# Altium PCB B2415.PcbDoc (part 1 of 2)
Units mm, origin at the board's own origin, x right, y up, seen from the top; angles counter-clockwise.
Board outline 20.32 x 48.65 mm, 4 copper layers (Top Layer, Internal 1, Internal 2, Bottom Layer), stack 0.62 mm thick; 96 components, 71 nets, 432 pads, 386 vias.
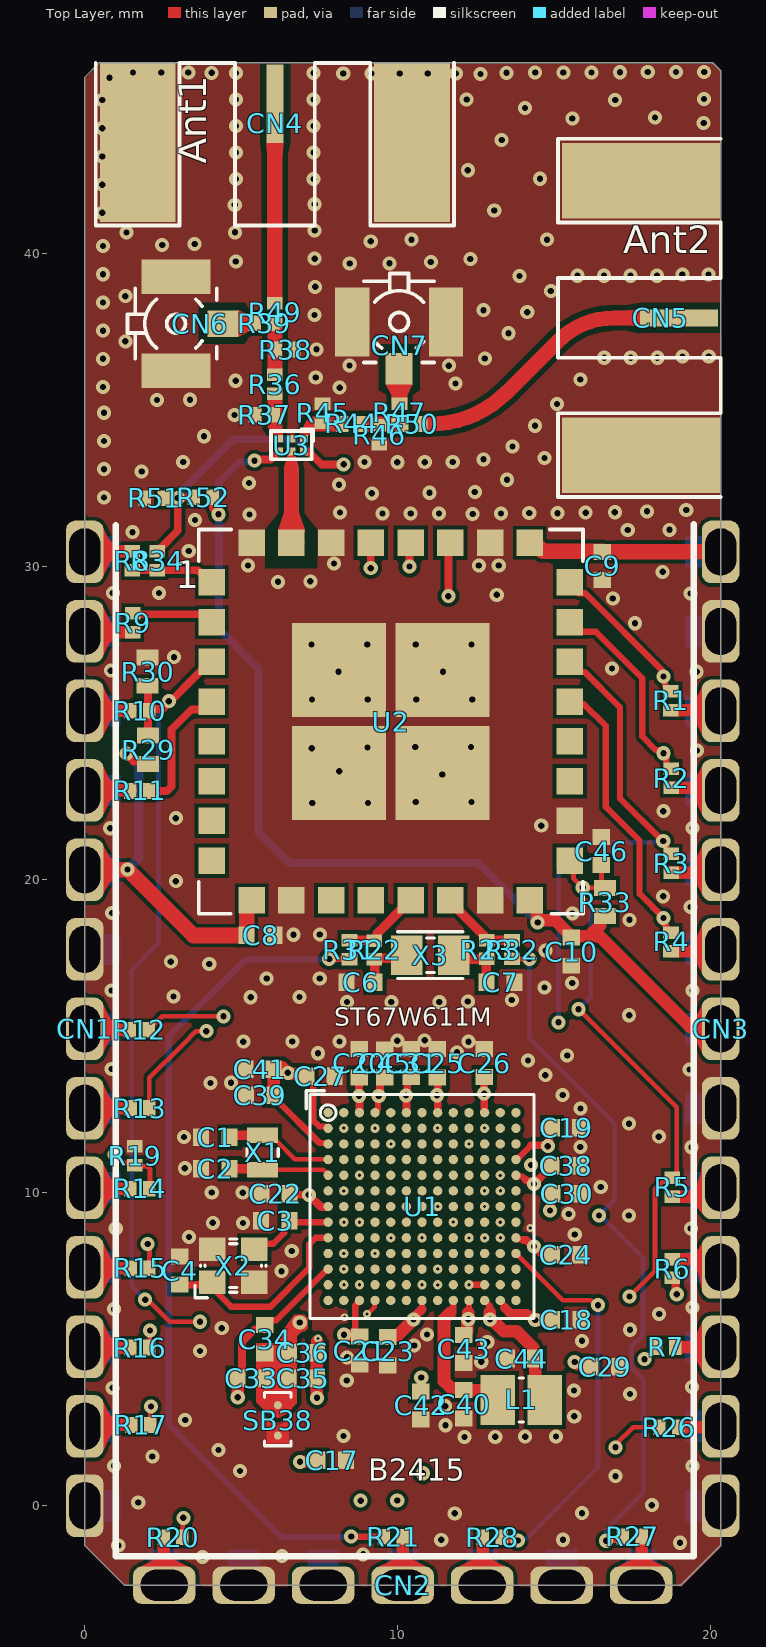
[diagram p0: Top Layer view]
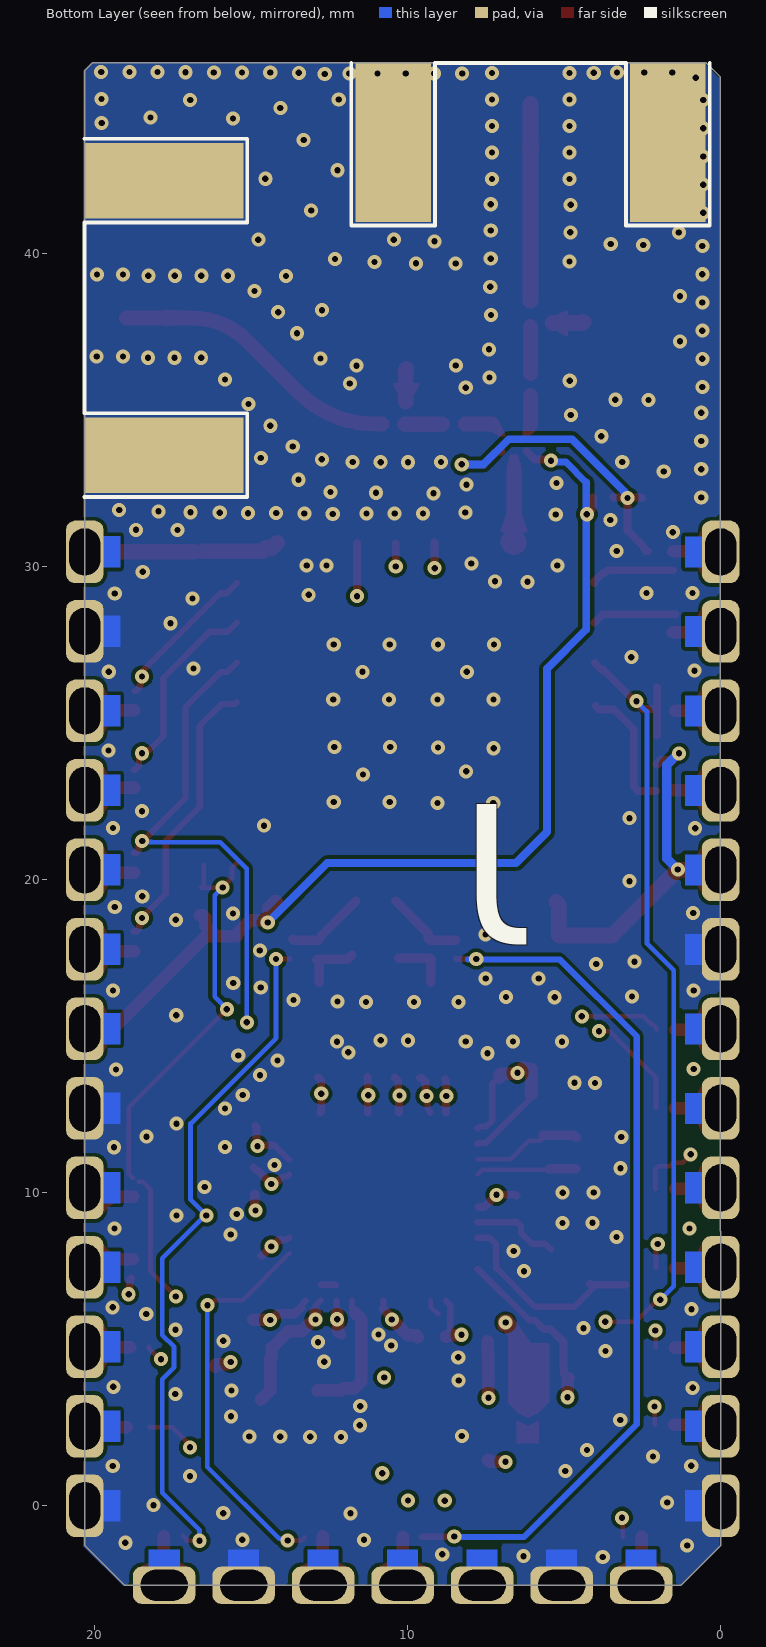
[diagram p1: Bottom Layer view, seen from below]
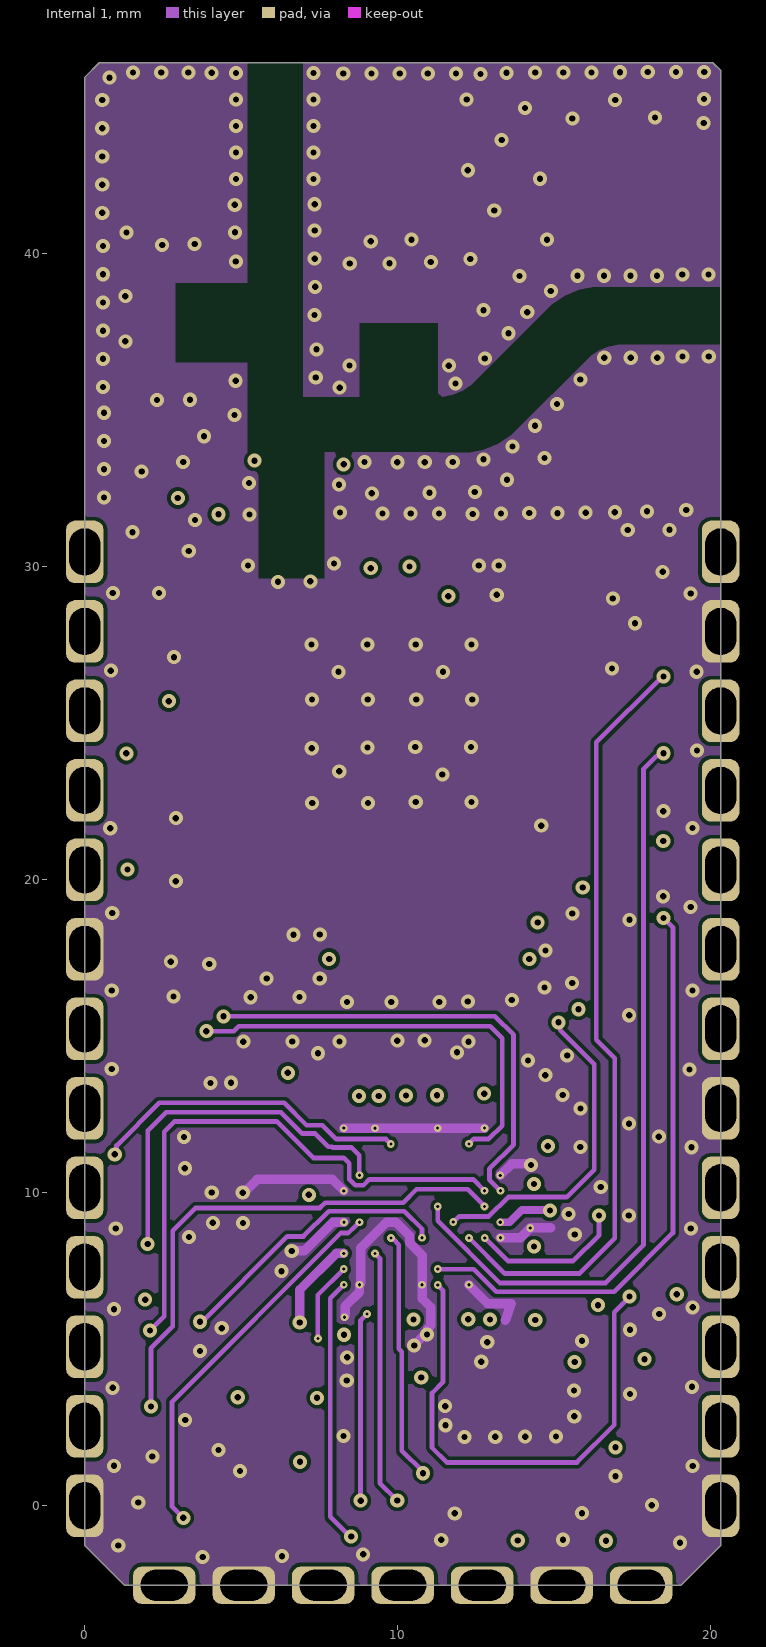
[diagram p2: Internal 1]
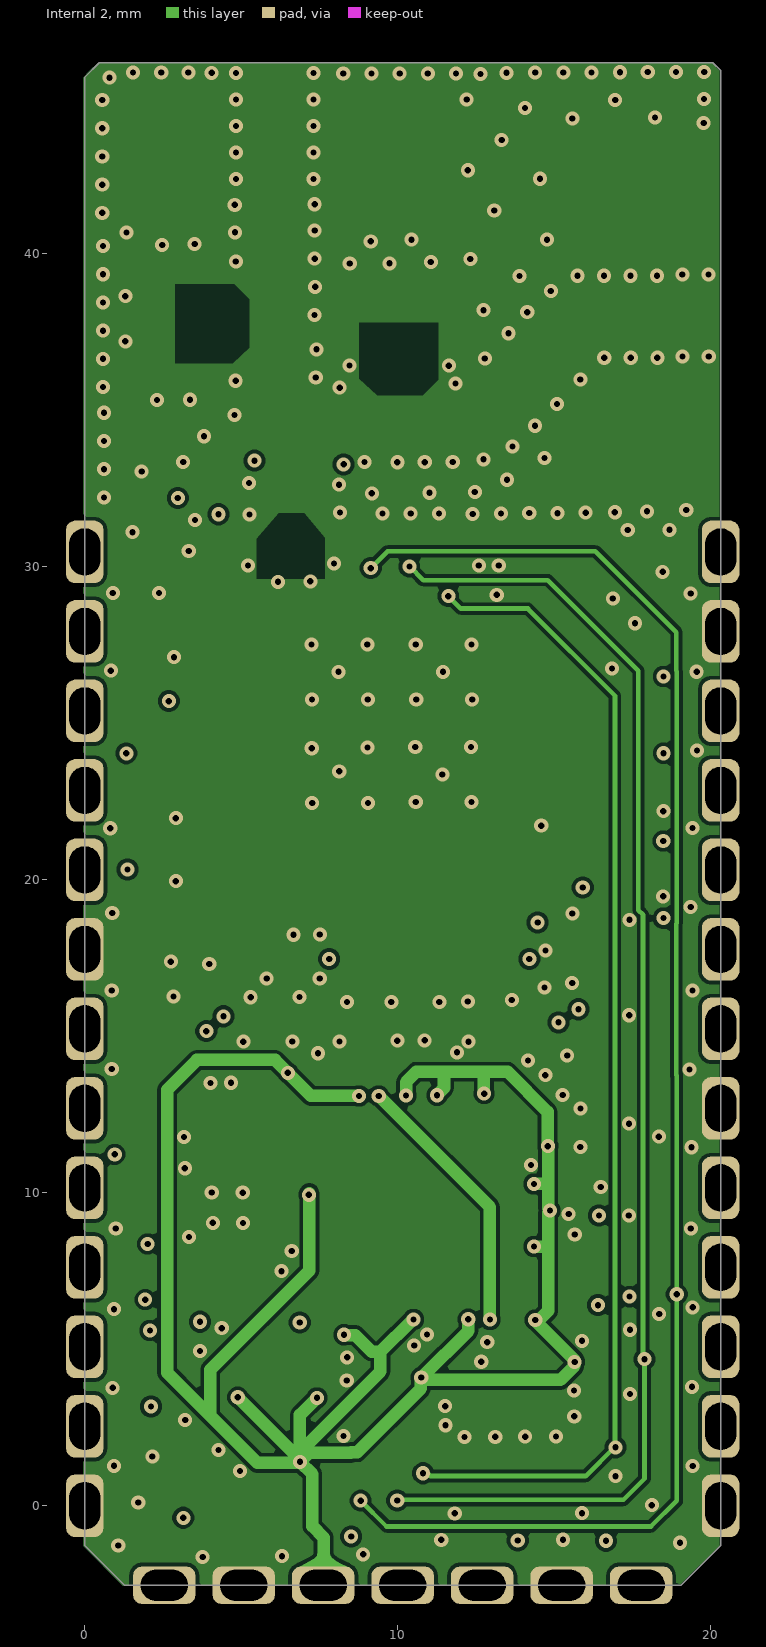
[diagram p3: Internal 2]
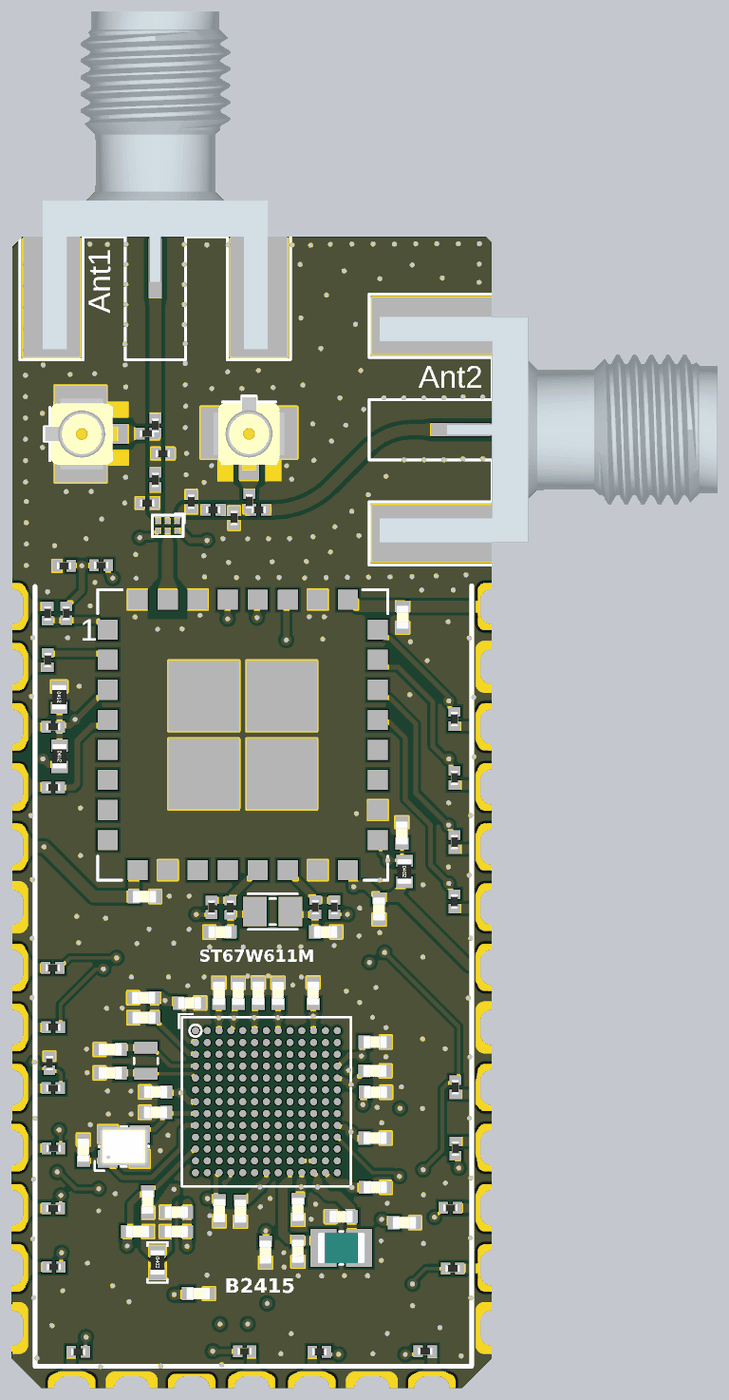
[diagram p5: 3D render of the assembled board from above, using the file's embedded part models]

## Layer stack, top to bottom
Top Solder: solder mask 0.0178, Solder Resist, Dk 3.2
Top Layer: signal copper 0.035
Dielectric 1: core 0.075, FR-4, Dk 4.5
Internal 1: signal copper 0.035
Dielectric 3: prepreg 0.335, Dk 4.5
Internal 2: signal copper 0.035
Dielectric 2: core 0.075, Dk 4.5
Bottom Layer: signal copper 0.03
Bottom Solder: solder mask 0.0178, Solder Resist, Dk 4.2

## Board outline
0,-1.27 0,8.758 0.008,8.767 0.008,45.651 0.467,46.11 20.07,46.11 20.32,45.86 20.32,-1.27 19.05,-2.54 1.27,-2.54

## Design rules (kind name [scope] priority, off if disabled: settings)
Clearance Clearance_SW [WithinRoom('STM32WW6_U575')] p1: gap=0.12 ignorepadtopadclearanceinfootprint=FALSE
Clearance "Schematic Clearance Constraint_4" [InNet('RF2')] p2: gap=0.17 ignorepadtopadclearanceinfootprint=FALSE
Clearance "Schematic Clearance Constraint_3" [InNet('RF1')] p3: gap=0.17 ignorepadtopadclearanceinfootprint=FALSE
Clearance "Schematic Clearance Constraint_20" [InNet('RF_Pin')] p4: gap=0.17 ignorepadtopadclearanceinfootprint=FALSE
Clearance "Schematic Clearance Constraint_19" [InNet('NetCN5_1')] p5: gap=0.17 ignorepadtopadclearanceinfootprint=FALSE
Clearance "Schematic Clearance Constraint_16" [InNet('RF1b')] p6: gap=0.17 ignorepadtopadclearanceinfootprint=FALSE
Clearance "Schematic Clearance Constraint_14" [InNet('RF2b')] p7: gap=0.17 ignorepadtopadclearanceinfootprint=FALSE
Clearance "Schematic Clearance Constraint_13" [InNet('NetCN7_1')] p8: gap=0.17 ignorepadtopadclearanceinfootprint=FALSE
Clearance "Schematic Clearance Constraint_8" [InNet('NetCN4_1')] p9: gap=0.17 ignorepadtopadclearanceinfootprint=FALSE
Clearance "Schematic Clearance Constraint_2" [InNet('NetCN6_1')] p10: gap=0.17 ignorepadtopadclearanceinfootprint=FALSE
Clearance [All] p11: gap=0.12 ignorepadtopadclearanceinfootprint=FALSE
ComponentClearance [All] p1 off: gap=0.2 collisioncheckmode=3 verticalgap=0.2 showdistances=FALSE
Height [All] p1 off: minheight=0 maxheight=25.4 prefheight=12.7
HoleSize [All] p1: absolutevalues=TRUE maxlimit=10 minlimit=0.025 maxpercent=80.000 minpercent=20.000
HoleToHoleClearance [All] p1: gap=0.127 allowstackedmicrovias=TRUE
MinimumSolderMaskSliver [All] p1: minsoldermaskwidth=0.1
PlaneConnect [All] p1: planeconnectstyle=Relief reliefexpansion=0.508 reliefentries=4 reliefconductorwidth=0.21 reliefairgap=0.21
PolygonConnect Path_RF [InNet('NetC12_2')] p1: connectstyle=Direct reliefconductorwidth=0.254 reliefentries=4 polygonreliefangle="90 Angle" airgapwidth=0.254
PolygonConnect PolygonConnect_via [IsVia] p2: connectstyle=Direct reliefconductorwidth=0.254 reliefentries=4 polygonreliefangle="90 Angle" airgapwidth=0.254
PolygonConnect General [All] p3: connectstyle=Direct reliefconductorwidth=0.2 reliefentries=4 polygonreliefangle="90 Angle" airgapwidth=0.2
RoutingVias [All] p1: holewidth=0.3 width=0.8 viastyle="Through Hole" minholewidth=0.1 minwidth=0.25 maxholewidth=3.5 maxwidth=6.5
SilkToSilkClearance [All] p1 off: silktosilkclearance=0.2
SilkToSolderMaskClearance [IsPad] p1 off: minsilkscreentomaskgap=0.2 clearancetoexposedcopper=TRUE
SolderMaskExpansion [All] p1: expansion=0.102 istentingtop=FALSE
Width [All] p1: maxlimit=6 minlimit=0.1 preferedwidth=0.3 minimp=50.000000 maximp=50.000000 favimp=50.000000
22 further rules are at their usual default settings.

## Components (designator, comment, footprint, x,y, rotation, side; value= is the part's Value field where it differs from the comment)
C1 "Capacitor" C0402 4.17,11.769 r0 top value=1.8pF
C2 "Capacitor" C0402 4.172,10.774 r0 top value=1.8pF
C3 "Capacitor" C0402 6.086,9.11 r0 top value=6.8pF
C4 "Capacitor" C0402 3.036,7.514 r270 top value=6.8pF
C6 "Capacitor" C0402 8.817,16.729 r180 top value=5.1pF
C7 "Capacitor" C0402 13.282,16.734 r180 top value=5.1pF
C8 "Capacitor" C0402 5.621,18.227 r0 top value=10uF
C9 "Capacitor" C0402 16.542,30.033 r270 top value=10uF
C10 "Capacitor" C0402 15.548,17.705 r90 top value=10uF
C17 "Capacitor" C0402 7.894,1.455 r180 top value=10uF
C18 "Capacitor" C0402 15.388,5.943 r180 top value=100nF
C19 "Capacitor" C0402 15.381,12.079 r180 top value=100nF
C20 "Capacitor" C0402 8.769,14.142 r270 top value=100nF
C21 "Capacitor" C0402 8.786,4.956 r90 top value=100nF
C22 "Capacitor" C0402 6.093,9.971 r0 top value=100nF
C23 "Capacitor" C0402 9.679,4.936 r90 top value=100nF
C24 "Capacitor" C0402 15.376,8.026 r180 top value=100nF
C25 "Capacitor" C0402 11.27,14.138 r270 top value=100nF
C26 "Capacitor" C0402 12.759,14.145 r270 top value=100nF
C27 "Capacitor" C0402 7.53,13.732 r180 top value=100nF
C29 "Capacitor" C0402 16.618,4.449 r180 top value=4.7uF
C30 "Capacitor" C0402 15.395,9.963 r180 top value=100nF
C31 "Capacitor" C0402 10.435,14.145 r270 top value=100nF
C33 "Capacitor" C0402 5.328,4.073 r180 top value=1uF
C34 "Capacitor" C0402 5.755,5.322 r90 top value=100nF
C35 "Capacitor" C0402 6.968,4.071 r0 top value=1uF
C36 "Capacitor" C0402 6.972,4.891 r0 top value=100nF
C38 "Capacitor" C0402 15.369,10.863 r180 top value=100nF
C39 "Capacitor" C0402 5.6,13.116 r0 top value=100nF
C40 "Capacitor" C0402 12.115,3.245 r90 top value=100pF
C41 "Capacitor" C0402 5.588,13.953 r0 top value=10uF
C42 "Capacitor" C0402 10.743,3.208 r90 top value=10uF
C43 "Capacitor" C0402 12.113,5.011 r90 top value=100nF
C44 "Capacitor" C0402 13.944,4.706 r0 top value=2.2uF
C45 "Capacitor" C0402 9.588,14.137 r270 top value=2.2uF
C46 "Capacitor" C0402 16.51,20.92 r270 top value=100nF
CART-1 "Comment" Sheetbox_6L2S 32.282,-5.454 r0 top
CN1 "" STAMPS_HOLES_X13 0,2.54 r0 top
CN2 "" Stamps_holes_x7 2.532,-2.577 r0 top
CN3 "" STAMPS_HOLES_X13 20.32,27.94 r180 top
CN4 "SMA-J-P-H-ST-EM1" CON_SMA-RF_CINCH_142-0701-851#1 6.076,46.105 r0 top value=Jack_SMA_142-0701-851
CN5 "SMA-J-P-H-ST-EM1" CON_SMA-RF_CINCH_142-0701-851#2 20.325,37.956 r270 top value=Jack_SMA_142-0701-851
CN6 "U.FL-R-SMT-1" CON_HRS_U.FL-R-SMT-1 2.917,37.773 r90 top value=Con_RF_U.FL-R-SMT-1
CN7 "U.FL-R-SMT-1" CON_HRS_U.FL-R-SMT-1 10.043,37.828 r0 top value=Con_RF_U.FL-R-SMT-1
Designator1 "Comment" PCB_SPECIFICATIONS 32.657,17.871 r0 top
L1 "Inductor" L0805_H0P9 13.948,3.381 r0 top value=2.2uH
R1 "Resistor" R0201_H0P23 18.731,25.726 r270 top value=0R
R2 "Resistor" R0201_H0P23 18.738,23.247 r270 top value=0R
R3 "Resistor" R0201_H0P23 18.74,20.529 r270 top value=0R
R4 "Resistor" R0201_H0P23 18.733,18.017 r270 top value=0R
R5 "Resistor" R0201_H0P23 18.77,10.177 r270 top value=0R
R6 "Resistor" R0201_H0P23 18.779,7.58 r90 top value=0R
R7 "Resistor" R0201_H0P23 18.565,5.071 r0 top value=0R
R8 "Resistor" R0201_H0P23 1.521,30.195 r270 top value=0R
R9 "Resistor" R0201_H0P23 1.532,28.215 r90 top value=0R
R10 "Resistor" R0201_H0P23 1.758,25.407 r0 top value=0R
R11 "Resistor" R0201_H0P23 1.757,22.84 r0 top value=0R
R12 "Resistor" R0201_H0P23 1.745,15.211 r0 top value=0R
R13 "Resistor" R0201_H0P23 1.764,12.708 r0 top value=0R
R14 "Resistor" R0201_H0P23 1.757,10.134 r0 top value=0R
R15 "Resistor" R0201_H0P23 1.769,7.593 r0 top value=0R
R16 "Resistor" R0201_H0P23 1.759,5.056 r0 top value=0R
R17 "Resistor" R0201_H0P23 1.788,2.579 r0 top value=0R
R19 "Resistor" R0201_H0P23 1.597,11.186 r90 top value=100K
R20 "Resistor" R0201_H0P23 2.819,-1.005 r0 top value=0R
R21 "Resistor" R0201_H0P23 9.859,-0.987 r180 top value=0R
R22 "Resistor" R0201_H0P23 9.248,17.76 r270 top value=0R
R23 "Resistor" R0201_H0P23 12.845,17.773 r270 top value=0R
R26 "Resistor" R0201_H0P23 18.661,2.512 r0 top value=0R
R27 "Resistor" R0201_H0P23 17.492,-0.981 r180 top value=0R
R28 "Resistor" R0201_H0P23 13.021,-1.006 r0 top value=0R
R29 "Resistor" R0402 2.027,24.156 r270 top value=33K
R30 "Resistor" R0402 2.01,26.653 r270 top value=33K
R31 "Resistor" R0201_H0P23 8.459,17.768 r90 top value=0R
R32 "Resistor" R0201_H0P23 13.652,17.773 r270 top value=0R
R33 "Resistor" R0402 16.62,19.289 r270 top value=33K
R34 "Resistor" R0201_H0P23 2.315,30.198 r90 top value=0R
R36 "Resistor" R0201_H0P23 6.076,35.832 r90 top value=0R
R37 "Resistor" R0201_H0P23 5.741,34.857 r0 top value=0R
R38 "Resistor" R0201_H0P23 6.401,36.946 r180 top value=0R
R39 "Resistor" R0201_H0P23 5.729,37.791 r0 top value=0R
R44 "Resistor" R0201_H0P23 8.522,34.567 r0 top value=0R
R45 "Resistor" R0201_H0P23 7.6,34.91 r270 top value=0R
R46 "Resistor" R0201_H0P23 9.414,34.22 r90 top value=0R
R47 "Resistor" R0201_H0P23 10.057,34.919 r270 top value=0R
R49 "Resistor" R0201_H0P23 6.076,38.129 r90 top value=0R
R50 "Resistor" R0201_H0P23 10.446,34.567 r0 top value=0R
R51 "Resistor" R0201_H0P23 2.218,32.199 r0 top value=100K
R52 "Resistor" R0201_H0P23 3.786,32.222 r0 top value=100K
SB38 "SB_ON" SOLDER-BRIDGE_R0402-0R 6.17,2.767 r270 top value=0R
U1 "STM32U575AII6QU" ICC_UFBGA169_7X7_P050 10.778,9.562 r0 top value=STM32U575AII6Q
U2 "ST67W611M1A6P" ST67W611M1A6P/B6P 9.756,25.101 r0 top
U3 "BGS12WN6" ICC_TSNP-6-10_0P7X1P1_P040 6.603,33.893 r270 top value=BGS12WN6E6327XTSA
X1 "XTAL_2_PINS" CRY_NX1610SE_2P 5.681,11.287 r90 top value=32.768kHz
X2 "XTAL_4_PINS" CRY_NX2016SA_4P 4.746,7.673 r0 top value=16MHz
X3 "XTAL_2_PINS" CRY_NX2012SA_2P 11.043,17.593 r180 top value=32.768KHz

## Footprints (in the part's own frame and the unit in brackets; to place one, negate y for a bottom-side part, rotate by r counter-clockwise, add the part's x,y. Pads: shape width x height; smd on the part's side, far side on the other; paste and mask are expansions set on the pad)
C0402 [mm]
  rect 0.51x0.56 smd mask+0.05: 1(-0.45,0) 2(0.45,0)
  body extent -0.5,-0.3 0.5,0.3, height 0.4
CON_HRS_U.FL-R-SMT-1 [mm] "MCD-01583"
  rect 0.85x1 smd mask+0.05: 1(0,-1.5)
  rect 1.1x2.2 smd mask+0.05: 2(-1.5,0) 3(1.5,0)
  silkscreen extent -1.12,-1.3 1.12,1.55, body extent -1.5,-1.6 1.5,1.5, height 1.25
CON_SMA-RF_CINCH_142-0701-851#1 [mil] "MCD-02072"
  rect 21.65x98.43 smd mask+1.97: 1(0,-51.48)
  rect 95x200 smd mask+1.97: 2(172.48,-100) 3(-172.48,-100)
  rect 95x200 smd far side mask+1.97: 4(-172.48,-100) 5(172.48,-100)
  silkscreen extent -225,-205 225,0, body extent -189,-187 189,376, height 161
CON_SMA-RF_CINCH_142-0701-851#2 [mil] "MCD-02072"
  rect 21.65x98.43 smd mask+1.97: 1(0,-52.51)
  rect 95x200 smd mask+1.97: 2(172.48,-100) 3(-172.48,-100)
  rect 95x200 smd far side mask+1.97: 4(-172.48,-100) 5(172.48,-100)
  silkscreen extent -225,-205 225,0, body extent -189,-187 189,376, height 161
CRY_NX1610SE_2P [mm] "MCD-02291"
  rect 0.5x1 smd mask+0.05: 1(-0.55,0) 2(0.55,0)
  silkscreen extent -0.13,-0.5 0.13,0.5, body extent -0.8,-0.5 0.8,0.5, height 0.45
CRY_NX2012SA_2P [mm]
  rect 1x1.25 smd mask+0.05: 1(-0.75,0) 2(0.75,0)
  silkscreen extent -1.05,-0.75 1.05,0.75, body extent -1.05,-0.63 1.05,0.63, height 0.6
CRY_NX2016SA_4P [mm]
  rect 0.85x0.75 smd mask+0.05: 1(-0.675,-0.525) 2(0.675,-0.525) 3(0.675,0.525) 4(-0.675,0.525)
  silkscreen extent -1.22,-1.02 1.05,0.85, body extent -1.05,-0.85 1.05,0.85, height 0.7
ICC_TSNP-6-10_0P7X1P1_P040 [mm] "MCD-03680"
  rect 0.25x0.25 smd paste-10 mask+0.038: 1(-0.2,0.4) 2(-0.2,0) 3(-0.2,-0.4) 4(0.2,-0.4) 5(0.2,0) 6(0.2,0.4)
  silkscreen extent -0.5,-0.65 0.45,0.7, body extent -0.38,-0.58 0.38,0.58, height 0.41
ICC_UFBGA169_7X7_P050 [mm]
  round 0.3 smd mask+0.05: A1(-3,3) A2(-2.5,3) A3(-2,3) A4(-1.5,3) A5(-1,3) A6(-0.5,3) A7(0,3) A8(0.5,3) A9(1,3) A10(1.5,3) A11(2,3) A12(2.5,3) A13(3,3) B1(-3,2.5) B2(-2.5,2.5) B3(-2,2.5) B4(-1.5,2.5) B5(-1,2.5) B6(-0.5,2.5) B7(0,2.5) B8(0.5,2.5) B9(1,2.5) B10(1.5,2.5) B11(2,2.5) B12(2.5,2.5) B13(3,2.5) C1(-3,2) C2(-2.5,2) C3(-2,2) C4(-1.5,2) C5(-1,2) C6(-0.5,2) C7(0,2) C8(0.5,2) C9(1,2) C10(1.5,2) C11(2,2) C12(2.5,2) C13(3,2) D1(-3,1.5) D2(-2.5,1.5) D3(-2,1.5) D4(-1.5,1.5) D5(-1,1.5) D6(-0.5,1.5) D7(0,1.5) D8(0.5,1.5) D9(1,1.5) D10(1.5,1.5) D11(2,1.5) D12(2.5,1.5) D13(3,1.5) E1(-3,1) E2(-2.5,1) E3(-2,1) E4(-1.5,1) E5(-1,1) E6(-0.5,1) E7(0,1) E8(0.5,1) E9(1,1) E10(1.5,1) E11(2,1) E12(2.5,1) E13(3,1) F1(-3,0.5) F2(-2.5,0.5) F3(-2,0.5) F4(-1.5,0.5) F5(-1,0.5) F6(-0.5,0.5) F7(0,0.5) F8(0.5,0.5) F9(1,0.5) F10(1.5,0.5) F11(2,0.5) F12(2.5,0.5) F13(3,0.5) G1(-3,0) G2(-2.5,0) G3(-2,0) G4(-1.5,0) G5(-1,0) G6(-0.5,0) G7(0,0) G8(0.5,0) G9(1,0) G10(1.5,0) G11(2,0) G12(2.5,0) G13(3,0) H1(-3,-0.5) H2(-2.5,-0.5) H3(-2,-0.5) H4(-1.5,-0.5) H5(-1,-0.5) H6(-0.5,-0.5) H7(0,-0.5) H8(0.5,-0.5) H9(1,-0.5) H10(1.5,-0.5) H11(2,-0.5) H12(2.5,-0.5) H13(3,-0.5) J1(-3,-1) J2(-2.5,-1) J3(-2,-1) J4(-1.5,-1) J5(-1,-1) J6(-0.5,-1) J7(0,-1) J8(0.5,-1) J9(1,-1) J10(1.5,-1) J11(2,-1) J12(2.5,-1) J13(3,-1) K1(-3,-1.5) K2(-2.5,-1.5) K3(-2,-1.5) K4(-1.5,-1.5) K5(-1,-1.5) K6(-0.5,-1.5) K7(0,-1.5) K8(0.5,-1.5) K9(1,-1.5) K10(1.5,-1.5) K11(2,-1.5) K12(2.5,-1.5) K13(3,-1.5) L1(-3,-2) L2(-2.5,-2) L3(-2,-2) L4(-1.5,-2) L5(-1,-2) L6(-0.5,-2) L7(0,-2) L8(0.5,-2) L9(1,-2) L10(1.5,-2) L11(2,-2) L12(2.5,-2) L13(3,-2) M1(-3,-2.5) M2(-2.5,-2.5) M3(-2,-2.5) M4(-1.5,-2.5) M5(-1,-2.5) M6(-0.5,-2.5) M7(0,-2.5) M8(0.5,-2.5) M9(1,-2.5) M10(1.5,-2.5) M11(2,-2.5) M12(2.5,-2.5) M13(3,-2.5) N1(-3,-3) N2(-2.5,-3) N3(-2,-3) N4(-1.5,-3) N5(-1,-3) N6(-0.5,-3) N7(0,-3) N8(0.5,-3) N9(1,-3) N10(1.5,-3) N11(2,-3) N12(2.5,-3) N13(3,-3)
  silkscreen extent -3.7,-3.57 3.57,3.7, body extent -3.57,-3.57 3.57,3.57, height 0.61
L0805_H0P9 [mm]
  rect 1.1x1.6 smd mask+0.05: 1(-0.75,0) 2(0.75,0)
  silkscreen extent -0.08,-0.7 0.08,0.7, body extent -1.07,-0.7 1.07,0.7, height 1.2
PCB_SPECIFICATIONS [mm]
R0201_H0P23 [mm]
  rect 0.4x0.5 smd mask+0.05: 1(-0.3,0) 2(0.3,0)
  body extent -0.32,-0.17 0.32,0.17, height 0.26
R0402 [mm]
  rect 0.51x0.7 smd mask+0.05: 1(-0.45,0) 2(0.45,0)
  body extent -0.52,-0.3 0.52,0.3, height 0.4
Sheetbox_6L2S [mil] "Sheetbox 6 layers / 2 silkscreens"
  round 20 on Mech16: 1(813.5,208.05) 1(2736.63,208.05)
SOLDER-BRIDGE_R0402-0R [mil] "MCD-01619"
  round 10 smd paste-393.7: 1(-17.72,0) 2(20.67,0)
  Top Layer region: 1.48,13.78 8.37,0 1.48,-13.78 30.51,-13.78 30.51,13.78
  Top Layer region: -30.51,-13.78 -30.51,13.78 -8.37,13.78 -1.48,0 -8.37,-13.78
  silkscreen extent -33,-17 33,17, body extent -20,-12 20,12, height 14
ST67W611M1A6P/B6P [mm]
  rect 0.85x0.85 smd mask+0.05: 1(-5.692,4.403) 2(-5.692,3.133) 3(-5.692,1.863) 4(-5.692,0.593) 5(-5.692,-0.677) 6(-5.692,-1.947) 7(-5.692,-3.217) 8(-5.692,-4.487) 9(-4.422,-5.757) 10(-3.152,-5.757) 11(-1.882,-5.757) 12(-0.612,-5.757) 13(0.658,-5.757) 14(1.928,-5.757) 15(3.198,-5.757) 16(4.468,-5.757) 17(5.738,-4.487) 18(5.738,-3.217) 19(5.738,-1.947) 20(5.738,-0.677) 21(5.738,0.593) 22(5.738,1.863) 23(5.738,3.133) 24(5.738,4.403) 25(4.468,5.673) 26(3.198,5.673) 27(1.928,5.673) 28(0.658,5.673) 29(-0.612,5.673) 30(-1.882,5.673) 31(-3.152,5.673) 32(-4.422,5.673)
  rect 3x3 smd mask+0.05: 33(-1.627,1.608) 34(-1.627,-1.692) 35(1.673,-1.692) 36(1.673,1.608)
  silkscreen extent -6.12,-6.18 6.16,6.1, body extent -6.12,-6.18 6.16,6.1, height 1.4
Stamps_holes_x7 [mm]
  rrect50% 2x1.2 hole 1 slot 1.5 at 0 deg mask+0.102: 1(0.008,0.037) 2(2.548,0.037) 3(5.088,0.037) 4(7.628,0.037) 5(10.168,0.037) 6(12.708,0.037) 7(15.248,0.037)
  Bottom Layer region: 8.132,-0.024 8.132,1.176 7.132,1.176 7.132,-0.024
  Bottom Layer region: 5.592,-0.024 5.592,1.176 4.592,1.176 4.592,-0.024
  Bottom Layer region: 3.052,-0.025 3.052,1.175 2.052,1.175 2.052,-0.025
  Bottom Layer region: 0.512,-0.024 0.512,1.176 -0.488,1.176 -0.488,-0.024
  Bottom Layer region: 10.672,-0.024 10.672,1.176 9.672,1.176 9.672,-0.024
  Bottom Layer region: 13.212,-0.024 13.212,1.176 12.212,1.176 12.212,-0.024
  Bottom Layer region: 15.752,-0.024 15.752,1.176 14.752,1.176 14.752,-0.024
STAMPS_HOLES_X13 [mm]
  rrect50% 1.2x2 hole 1 slot 1.5 at 90 deg mask+0.102: 1(0,27.94) 2(0,25.4) 3(0,22.86) 4(0,20.32) 5(0,17.78) 6(0,15.24) 7(0,12.7) 8(0,10.16) 9(0,7.62) 10(0,5.08) 11(0,2.54) 12(0,0) 13(0,-2.54)
  Bottom Layer region: -0.062,-3.04 1.138,-3.04 1.138,-2.04 -0.062,-2.04
  Bottom Layer region: -0.062,19.817 1.138,19.817 1.138,20.817 -0.062,20.817
  Bottom Layer region: -0.062,22.357 1.138,22.357 1.138,23.357 -0.062,23.357
  Bottom Layer region: -0.062,24.897 1.138,24.897 1.138,25.897 -0.062,25.897
  Bottom Layer region: -0.062,27.437 1.138,27.437 1.138,28.437 -0.062,28.437
  Bottom Layer region: -0.062,17.277 1.138,17.277 1.138,18.277 -0.062,18.277
  Bottom Layer region: -0.062,14.737 1.138,14.737 1.138,15.737 -0.062,15.737
  Bottom Layer region: -0.062,12.197 1.138,12.197 1.138,13.197 -0.062,13.197
  Bottom Layer region: -0.062,9.657 1.138,9.657 1.138,10.657 -0.062,10.657
  Bottom Layer region: -0.062,7.12 1.138,7.12 1.138,8.12 -0.062,8.12
  Bottom Layer region: -0.062,4.58 1.138,4.58 1.138,5.58 -0.062,5.58
  Bottom Layer region: -0.062,2.04 1.138,2.04 1.138,3.04 -0.062,3.04
  Bottom Layer region: -0.062,-0.5 1.138,-0.5 1.138,0.5 -0.062,0.5

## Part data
C1 C2: library part MCD-02995, "Capacitor, MLCC, 1.8pF, 50V, C0G, +/-0.25pF, 0402, T=0.5mm", Manufacturer=MURATA, Manufacturer_Part_Number=GRM1555C1H1R8CA01, Package=0402
C3 C4: library part MCD-00674, "Capacitor, MLCC, 6.8pF, 50V, NPO, +/-0.25pF, 0402, T=0.5mm", Manufacturer=YAGEO, Manufacturer_Part_Number=CC0402CRNPO9BN6R8, Package=0402
C6 C7: library part MCD-00003, "Capacitor, MLCC, 5.1pF, 50V, NPO, +/-0.25pF, 0402, T=0.5mm", Manufacturer=YAGEO, Manufacturer_Part_Number=CC0402CRNPO9BN5R1, Package=0402
C8 C9 C10 C17 C41 C42: library part MCD-01532, "Capacitor, MLCC, 10uF, 10V, X5R, +/-20%, 0402, T=0.5mm", Manufacturer=MURATA, Manufacturer_Part_Number=GRM155R61A106ME11, Package=0402
C18 C19 C20 C21 C22 C23 C24 C25 C26 C27 C30 C31 C34 C36 C38 C39 C43: library part MCD-00102, "Capacitor, MLCC, 100nF, 16V, X7R, +/-10%, 0402, T=0.5mm", Manufacturer=YAGEO, Manufacturer_Part_Number=CC0402KRX7R7BB104, Package=0402
C29: library part MCD-03816, "Capacitor, MLCC, 4.7uF, 6V3, X6S, +/-22%, 0402, T=0.5mm", Manufacturer=MURATA, Manufacturer_Part_Number=GRM155C80J475ME01, Package=0402
C33 C35: library part MCD-00095, "Capacitor, MLCC, 1uF, 25V, X5R, +/-10%, 0402, T=0.5mm", Manufacturer=MURATA, Manufacturer_Part_Number=GRM155R61E105KA12, Package=0402
C40: library part MCD-00205, "Capacitor, MLCC, 100pF, 50V, NPO, +/-5%, 0402, T=0.5mm", Manufacturer=YAGEO, Manufacturer_Part_Number=CC0402JRNPO9BN101, Package=0402
C44 C45: library part MCD-01823, "Capacitor, MLCC, 2.2uF, 6V3, X5R,+/-10%, 0402, T=0.5mm", Manufacturer=MURATA, Manufacturer_Part_Number=GRM155R60J225KE95D, Package=0402
C46: library part MCD-00006, "Capacitor, MLCC, 100nF, 16V, X7R, +/-10%, 0402, T=0.5mm", Manufacturer=YAGEO, Manufacturer_Part_Number=CC0402KRX7R7BB104, Package=0402
CN1 CN3: library part hole_2_54_x13
CN2: library part hole_2_54_x7
CN4 CN5: library part MCD-02072, "Jack_SMA, VR, PCB edge, 50R, T=7.92mm", Manufacturer=CINCH, Manufacturer_Part_Number=142-0701-851
CN6 CN7: library part MCD-01583, "Connector_RF, 0Hz to 6GHz, 50R, VR, SMD, T= 1.25mm", Manufacturer=HIROSE
L1: library part MCD-01060, "Inductor, 2.2uH, +/-20%, 0.7A, 0R156, 0805, T=0.9mm", Manufacturer=MURATA, Manufacturer_Part_Number=LQM21PN2R2MGH, Package=0805
R1 R2 R3 R4 R5 R6 R7 R8 R9 R10 R11 R12 R13 R14 R15 R16 R17 R20 R21 R22 R23 R26 R27 R28 R31 R32 R34 R36 R37 R38 R39 R44 R45 R46 R47 R49 R50: library part MCD-02450, "Resistor, 0R, 0201, 1/20W", Manufacturer=YAGEO, Manufacturer_Part_Number=RC0201JR-070RP, Package=0201
R19 R51 R52: library part MCD-03041, "Resistor, 100K, 0201, +/-1%, 1/20W", Manufacturer=YAGEO, Manufacturer_Part_Number=RC0201FR-07100KL, Package=0201
R29 R30 R33: library part MCD-00258, "Resistor, 33K, 0402, +/-1%, 1/16W", Manufacturer=YAGEO, Manufacturer_Part_Number=RC0402FR-0733KL, Package=0402
SB38: library part MCD-01618, "Resistor, 0R, SB0402, 5%, 0.063W", Manufacturer=YAGEO, Manufacturer_Part_Number=RC0402JR-070RL, Package=0402
U1: library part MCD-01928, "MCU, ARM Cortex-M33 32-bit, 2MB Flash, 786KB RAM, With Crypto, SMPS", Manufacturer=STMICROELECTRONICS, Manufacturer_HQ_COO=EU, Manufacturer_Part_Number=STM32U575AII6Q, Package=BGA-169
U2: library part ST67W611M_P, "STM32WW611MNA6P"
U3: library part MCD-03680, "IC, Wideband SPDT Diversity Switch with High Switching Speed", Manufacturer=INFINEON, Manufacturer_Part_Number=BGS12WN6E6327XTSA, Package=TSNP-6-10
X1: library part MCD-02291, "Crystal, 32.768kHz, 9pF, +/-20ppm, 70KR, 1.6x1.0mm", Manufacturer=NDK, Manufacturer_Part_Number=NX1610SE-32.768KHz-EXS00A-MU01499, Package=1.6x1.0mm
X2: library part MCD-01476, "Crystal, 16 MHz, 8pF, +/-20ppm, 200R, 2.0x1.6mm", Manufacturer=NDK, Manufacturer_Part_Number=NX2016SA-16MHz-EXS00A-CS07826, Package=2.0x1.6mm
X3: library part MCD-01479, "Crystal, 32.768kHz, 6pF, +/-20ppm, 80K, 2.05x1.2mm", Manufacturer=NDK, Manufacturer_Part_Number=NX2012SA-32.768KHz-EXS00A-MU00527, Package=2.05x1.2mm

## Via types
v1: diameter 0.45, hole 0.2, Top Layer to Bottom Layer, tented both sides, 351 vias
v2: diameter 0.25, hole 0.1, Top Layer to Internal 1, tented top, 35 vias

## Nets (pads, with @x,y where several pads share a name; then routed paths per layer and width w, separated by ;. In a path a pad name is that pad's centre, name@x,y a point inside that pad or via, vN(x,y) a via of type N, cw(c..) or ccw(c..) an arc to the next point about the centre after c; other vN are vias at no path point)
16M_U5_IN: C3.2 U1.H1 X2.3 | length 2.8
  Top Layer w0.2: X2.3@5.421,8.198 5.598,8.375 6.029,8.375 6.381,8.727 6.381,8.93 6.525,9.074 C3.2@6.599,9.074 ; C3.2@6.599,9.062 U1.H1@7.778,9.062
16M_U5_OUT: C4.2 U1.J1 X2.1 | length 6.5
  Top Layer w0.2: X2.1@4.062,6.976 4.676,6.362 5.936,6.362 7.176,7.602 7.176,8.355 7.379,8.558 ; 7.379,8.562 U1.J1@7.778,8.562
  Top Layer w0.25: C4.2@3.036,7.064 4.149,7.064 X2.1@4.182,7.096
32k_U5_IN: C1.2 U1.D1 X1.2 | length 3.5
  Top Layer w0.15: X1.2@5.639,11.795 5.771,11.662 6.127,11.662 6.713,11.077 U1.D1@7.762,11.077
  Top Layer w0.3: C1.2@4.62,11.769 4.689,11.837 X1.2@5.681,11.837
32k_U5_OUT: C2.2 U1.E1 X1.1 | length 3.1
  Top Layer w0.15: X1.1@5.596,10.737 X1.1@5.681,10.737 7.614,10.737 U1.E1@7.764,10.587
  Top Layer w0.3: C2.2@4.622,10.774 5.448,10.774 X1.1@5.474,10.747
AGND: C33.1 C34.1 C35.1 C36.1 SB38.1 U1.K2 | length 2.9
  Internal 1 w0.3: v1(6.871,5.855) 6.871,6.9 8.036,8.065 v2(8.276,8.065)
ANT_SEL: R34.2 R51.2 R52.1 U3.6 | length 10.9
  Top Layer w0.25: R34.2@2.315,30.498 2.365,30.498 2.44,30.573 2.44,30.623 2.974,31.157 v1(2.974,32.204) ; R51.2@2.518,32.199 2.593,32.215 3.362,32.215 ccw(c3.362,32.465) R52.1@3.449,32.231 ; U3.6@7.003,33.693 7.146,33.693 7.562,33.277 v1(8.273,33.277)
  Bottom Layer w0.25: v1(2.974,32.204) 2.974,32.259 3.074,32.359 3.074,32.405 4.75,34.081 6.772,34.081 7.576,33.277 v1(8.273,33.277)
BOOT0_U5: R14.2 R19.1 U1.C5 | length 12.1
  Top Layer w0.15: v1@0.971,11.199 1.21,10.96 1.523,10.96 R19.1@1.597,10.886 1.631,10.852 1.984,10.852 2.086,10.751 2.086,10.133 R14.2@2.078,10.125
  Internal 1 w0.15: v1(0.959,11.23) 1.016,11.287 1.016,11.509 2.385,12.877 6.372,12.877 7.086,12.163 7.595,12.163 8.041,11.717 9.625,11.717 v2(9.78,11.561)
"BOOT_WW6 / JTDO": R10.2 R29.1 R30.2 U1.J7 U2.3 | length 35.1
  Top Layer w0.15: v1(1.931,6.586) 2.011,6.586 2.716,5.88 v1(3.686,5.88)
  Top Layer w0.25: R29.1@2.027,24.606 2.027,26.14 R30.2@2.039,26.152 ; R10.2@2.058,25.457 2.488,25.457 3.75,26.718 3.812,26.718 U2.3@4.025,26.931
  Internal 1 w0.15: v1@3.685,5.822 6.47,8.607 6.989,8.607 7.794,9.412 10.21,9.412 10.778,8.844 v2(10.778,8.564)
  Bottom Layer w0.15: v1(1.931,6.586) 1.5,7.017 1.5,17.115 2.354,17.969 2.354,25.379 v1(2.687,25.711)
CHIP_EN_U5: C46.2 R5.1 R33.1 U1.M8 U2.17 | length 33.7
  Top Layer w0.15: U2.17@15.49,20.507 15.617,20.38 15.617,20.055 15.919,19.753 16.6,19.753 16.603,19.756 16.515,19.844 C46.2@16.515,20.474 ; v1(15.778,15.866) 18.915,12.729 18.915,10.602 18.79,10.477 R5.1@18.77,10.477 ; v1(17.409,6.69) 18.219,7.5 18.219,10.107 18.464,10.352 R5.1@18.595,10.352
  Internal 1 w0.15: v2(11.281,7.056) 11.446,6.89 11.446,3.953 11.096,3.602 11.096,1.859 11.57,1.385 15.727,1.385 16.922,2.581 16.922,6.188 v1@17.412,6.677
  Bottom Layer w0.15: v1(15.778,15.866) 15.778,15.883 16.167,16.271 16.167,19.505 v1(15.913,19.759)
Device_Ready_U5: R4.1 U1.L8 U2.21 | length 27.7
  Top Layer w0.2: U2.21@15.461,25.673 15.517,25.617 15.951,25.617 16.646,24.922 16.646,22.331 17.728,21.249 17.728,19.55 v1(18.494,18.785) ; v1@18.41,18.701 18.41,18.699 18.583,18.525 18.583,18.417 18.638,18.362 R4.1@18.77,18.362
  Internal 1 w0.15: v2(11.279,7.562) 12.43,7.562 13.15,6.842 16.92,6.842 18.796,8.718 18.796,18.483 v1(18.494,18.785)
Device_Wakeup_U5: R27.2 R32.2 U1.J11 | length 27.4
  Top Layer w0.15: R32.2@13.756,17.473 v1(14.206,17.473) ; v1(16.656,-1.118) 17.067,-1.118 17.067,-1.073 R27.2@17.189,-0.951
  Internal 1 w0.15: v2(12.781,8.56) 13.518,7.822 15.614,7.822 16.434,8.643 v1(16.434,9.279)
  Bottom Layer w0.15: v1(14.206,17.473) 14.206,14.944 16.938,12.212 16.938,9.783 v1(16.434,9.279) 16.473,9.279 17.841,7.911 17.841,5.45 17.467,5.076 17.467,4.425 17.845,4.047 17.845,0.417 16.651,-0.777 16.651,-1.113 v1(16.656,-1.118)
Ext_32k_U5: R21.2 R31.1 U1.M2 | length 36.4
  Top Layer w0.2: v1@7.772,17.44 7.801,17.468 R31.1@8.459,17.468 ; v1(8.513,-0.98) 8.525,-0.991 9.555,-0.991 R21.2@9.559,-0.987
  Internal 1 w0.15: v2(8.279,7.063) 7.848,6.632 7.848,-0.354 8.474,-0.98 v1(8.513,-0.98)
  Bottom Layer w0.2: 8.067,17.456 5.141,17.456 2.684,14.999 2.684,2.603 6.282,-0.995 8.497,-0.995 v1(8.513,-0.98)
  other v1: 7.811,17.475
